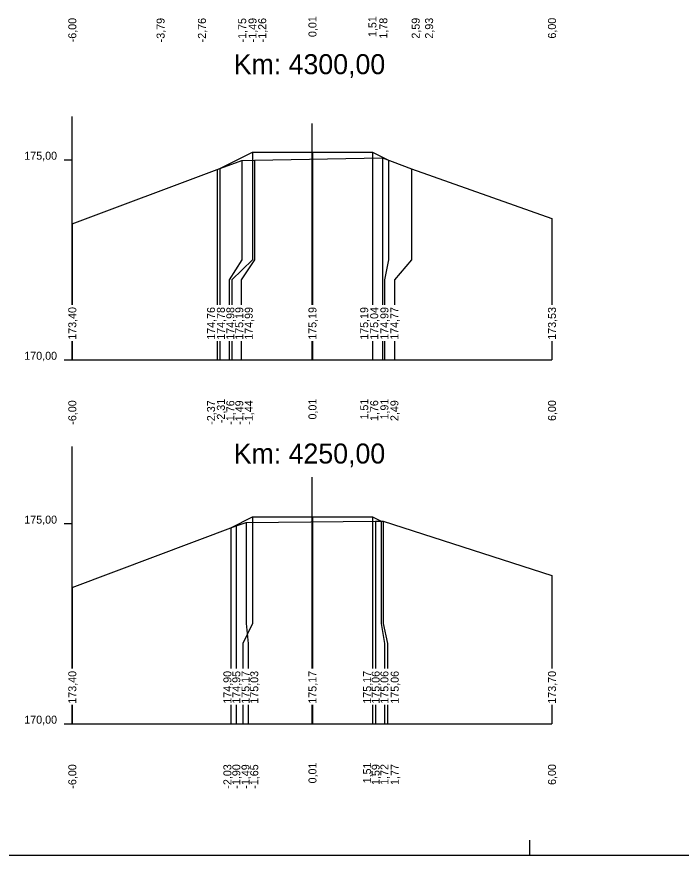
# Model space of a CAD drawing. Extents: x -614174 to -599765, y -1185887 to -1181080.
# Drawn here: x -600977.78 to -600961.16, y -1184533.61 to -1184512.65 of the extents above; entities that cross this region are included whole.
import ezdxf

# ---------------------------------------------------------------- set-up
doc = ezdxf.new("R2010")
doc.units = 0
for name, color, linetype in [('11', 7, 'Continuous'), ('16', 7, 'Continuous'), ('21', 7, 'Continuous'), ('28', 7, 'Continuous'), ('59', 7, 'Continuous'), ('8', 7, 'Continuous'), ('návrh', 7, 'Continuous')]:
    doc.layers.add(name, color=color, linetype=linetype)

msp = doc.modelspace()

# ---------------------------------------------------------------- linework, layer by layer
for points in [[(-600972.699, -1184516.446), (-600971.881, -1184516.037), (-600970.381, -1184516.037), (-600968.881, -1184516.037), (-600968.476, -1184516.239)], [(-600971.881, -1184516.037), (-600971.881, -1184516.037), (-600971.881, -1184516.037)], [(-600970.381, -1184516.037), (-600970.381, -1184516.037), (-600970.381, -1184516.037)], [(-600968.881, -1184516.037), (-600968.881, -1184516.037), (-600968.881, -1184516.037)], [(-600976.389, -1184517.827), (-600972.762, -1184516.469), (-600972.148, -1184516.243), (-600971.829, -1184516.236), (-600968.631, -1184516.182), (-600967.904, -1184516.452), (-600964.389, -1184517.699)], [(-600972.699, -1184516.446), (-600972.699, -1184516.446), (-600972.7, -1184516.446)], [(-600976.389, -1184526.919), (-600972.286, -1184525.374), (-600972.042, -1184525.291), (-600968.8, -1184525.264), (-600968.616, -1184525.264), (-600964.389, -1184526.622)], [(-600972.419, -1184525.424), (-600971.881, -1184525.156), (-600970.381, -1184525.156), (-600968.881, -1184525.156), (-600968.664, -1184525.264)], [(-600971.881, -1184525.156), (-600971.881, -1184525.156), (-600971.881, -1184525.156)], [(-600970.381, -1184525.156), (-600970.381, -1184525.156), (-600970.381, -1184525.156)], [(-600968.881, -1184525.156), (-600968.881, -1184525.156), (-600968.881, -1184525.156)], [(-600972.419, -1184525.424), (-600972.419, -1184525.424), (-600972.419, -1184525.424)]]:
    msp.add_lwpolyline(points)
at = {"layer": '11'}
for points in [[(-600971.881, -1184516.037), (-600971.881, -1184518.726), (-600972.399, -1184519.226), (-600972.399, -1184519.849)], [(-600970.381, -1184516.037), (-600970.381, -1184518.726), (-600970.381, -1184519.226), (-600970.381, -1184519.849)], [(-600968.881, -1184516.037), (-600968.881, -1184518.726), (-600968.881, -1184519.226), (-600968.881, -1184519.849)], [(-600972.148, -1184516.243), (-600972.148, -1184518.726), (-600972.462, -1184519.226), (-600972.462, -1184519.849)], [(-600971.829, -1184516.236), (-600971.829, -1184518.726), (-600972.162, -1184519.226), (-600972.162, -1184519.849)], [(-600968.631, -1184516.182), (-600968.631, -1184518.726), (-600968.631, -1184519.226), (-600968.631, -1184519.849)], [(-600968.476, -1184516.239), (-600968.476, -1184518.726), (-600968.581, -1184519.226), (-600968.581, -1184519.849)], [(-600972.762, -1184516.469), (-600972.762, -1184518.726), (-600972.762, -1184519.226), (-600972.762, -1184519.849)], [(-600972.699, -1184516.446), (-600972.699, -1184518.726), (-600972.699, -1184519.226), (-600972.699, -1184519.849)], [(-600967.904, -1184516.452), (-600967.904, -1184518.726), (-600968.331, -1184519.226), (-600968.331, -1184519.849)], [(-600964.389, -1184517.699), (-600964.389, -1184518.726), (-600964.389, -1184519.226), (-600964.389, -1184519.849)], [(-600976.389, -1184517.827), (-600976.389, -1184518.726), (-600976.389, -1184519.226), (-600976.389, -1184519.849)], [(-600976.389, -1184520.757), (-600976.389, -1184521.226)], [(-600972.762, -1184520.757), (-600972.762, -1184521.226)], [(-600972.699, -1184520.757), (-600972.699, -1184521.226)], [(-600972.462, -1184520.757), (-600972.462, -1184521.226)], [(-600972.399, -1184520.757), (-600972.399, -1184521.226)], [(-600972.162, -1184520.757), (-600972.162, -1184521.226)], [(-600970.381, -1184520.757), (-600970.381, -1184521.226)], [(-600968.881, -1184520.757), (-600968.881, -1184521.226)], [(-600968.631, -1184520.757), (-600968.631, -1184521.226)], [(-600968.581, -1184520.757), (-600968.581, -1184521.226)], [(-600968.331, -1184520.757), (-600968.331, -1184521.226)], [(-600964.389, -1184520.757), (-600964.389, -1184521.226)], [(-600971.881, -1184525.156), (-600971.881, -1184527.822), (-600972.119, -1184528.322), (-600972.119, -1184528.945)], [(-600972.042, -1184525.291), (-600972.042, -1184527.822), (-600971.986, -1184528.322), (-600971.986, -1184528.945)], [(-600970.381, -1184525.156), (-600970.381, -1184527.822), (-600970.381, -1184528.322), (-600970.381, -1184528.945)], [(-600968.881, -1184525.156), (-600968.881, -1184527.822), (-600968.881, -1184528.322), (-600968.881, -1184528.945)], [(-600968.8, -1184525.264), (-600968.8, -1184527.822), (-600968.8, -1184528.322), (-600968.8, -1184528.945)], [(-600968.664, -1184525.264), (-600968.664, -1184527.822), (-600968.581, -1184528.322), (-600968.581, -1184528.945)], [(-600968.616, -1184525.264), (-600968.616, -1184527.822), (-600968.5, -1184528.322), (-600968.5, -1184528.945)], [(-600972.419, -1184525.424), (-600972.419, -1184527.822), (-600972.419, -1184528.322), (-600972.419, -1184528.945)], [(-600972.286, -1184525.374), (-600972.286, -1184527.822), (-600972.286, -1184528.322), (-600972.286, -1184528.945)], [(-600964.389, -1184526.622), (-600964.389, -1184527.822), (-600964.389, -1184528.322), (-600964.389, -1184528.945)], [(-600976.389, -1184526.919), (-600976.389, -1184527.822), (-600976.389, -1184528.322), (-600976.389, -1184528.945)], [(-600976.389, -1184529.853), (-600976.389, -1184530.322)], [(-600972.419, -1184529.853), (-600972.419, -1184530.322)], [(-600972.286, -1184529.853), (-600972.286, -1184530.322)], [(-600972.119, -1184529.853), (-600972.119, -1184530.322)], [(-600971.986, -1184529.853), (-600971.986, -1184530.322)], [(-600970.381, -1184529.853), (-600970.381, -1184530.322)], [(-600968.881, -1184529.853), (-600968.881, -1184530.322)], [(-600968.8, -1184529.853), (-600968.8, -1184530.322)], [(-600968.581, -1184529.853), (-600968.581, -1184530.322)], [(-600968.5, -1184529.853), (-600968.5, -1184530.322)], [(-600964.389, -1184529.853), (-600964.389, -1184530.322)]]:
    msp.add_lwpolyline(points, dxfattribs=at)
at = {"layer": '16'}
for p, q in [((-600976.389, -1184521.226), (-600964.389, -1184521.226)), ((-600976.389, -1184530.322), (-600964.389, -1184530.322))]:
    msp.add_line(p, q, dxfattribs=at)
for points in [[(-600968.476, -1184516.239), (-600968.476, -1184516.239), (-600968.476, -1184516.239)], [(-600968.664, -1184525.264), (-600968.664, -1184525.264), (-600968.664, -1184525.264)]]:
    msp.add_lwpolyline(points, dxfattribs=at)
at = {"layer": '21'}
for p, q in [((-600976.589, -1184516.226), (-600976.389, -1184516.226)), ((-600976.589, -1184521.226), (-600976.389, -1184521.226)), ((-600976.589, -1184525.322), (-600976.389, -1184525.322)), ((-600976.589, -1184530.322), (-600976.389, -1184530.322))]:
    msp.add_line(p, q, dxfattribs=at)
at = {"layer": '28'}
for p, q in [((-600970.389, -1184519.849), (-600970.389, -1184515.319)), ((-600970.389, -1184521.226), (-600970.389, -1184520.757)), ((-600970.389, -1184528.945), (-600970.389, -1184524.163)), ((-600970.389, -1184530.322), (-600970.389, -1184529.853))]:
    msp.add_line(p, q, dxfattribs=at)
at = {"layer": '8'}
for p, q in [((-600976.389, -1184519.849), (-600976.389, -1184515.148)), ((-600976.389, -1184521.226), (-600976.389, -1184520.757)), ((-600976.389, -1184528.945), (-600976.389, -1184523.397)), ((-600976.389, -1184530.322), (-600976.389, -1184529.853))]:
    msp.add_line(p, q, dxfattribs=at)
at = {"layer": 'návrh'}
for p, q in [((-600964.944, -1184533.61), (-600964.944, -1184533.23)), ((-600985.944, -1184533.61), (-600964.944, -1184533.61)), ((-600964.944, -1184533.61), (-600943.944, -1184533.61))]:
    msp.add_line(p, q, dxfattribs=at)

# ---------------------------------------------------------------- texts
at = {"layer": '16'}
for s, p in [('173,40', (-600976.289, -1184520.726)), ('174,76', (-600972.818, -1184520.726)), ('174,78', (-600972.572, -1184520.726)), ('174,98', (-600972.335, -1184520.726)), ('175,19', (-600972.112, -1184520.726)), ('174,99', (-600971.875, -1184520.726)), ('175,19', (-600970.281, -1184520.726)), ('175,19', (-600968.986, -1184520.726)), ('175,04', (-600968.736, -1184520.726)), ('174,99', (-600968.481, -1184520.726)), ('174,77', (-600968.231, -1184520.726)), ('173,53', (-600964.289, -1184520.726)), ('173,40', (-600976.289, -1184529.822)), ('174,90', (-600972.409, -1184529.822)), ('174,95', (-600972.186, -1184529.822)), ('175,17', (-600971.956, -1184529.822)), ('175,03', (-600971.737, -1184529.822)), ('175,17', (-600970.281, -1184529.822)), ('175,17', (-600968.913, -1184529.822)), ('175,06', (-600968.7, -1184529.822)), ('175,06', (-600968.481, -1184529.822)), ('175,06', (-600968.223, -1184529.822)), ('173,70', (-600964.289, -1184529.822))]:
    msp.add_text(s, height=0.2, rotation=90, dxfattribs=at).set_placement(p)
at = {"layer": '21'}
for s, p in [('175,00', (-600977.589, -1184516.226)), ('170,00', (-600977.589, -1184521.226)), ('175,00', (-600977.589, -1184525.322)), ('170,00', (-600977.589, -1184530.322))]:
    msp.add_text(s, height=0.2, dxfattribs=at).set_placement(p)
at = {"layer": '28'}
for s, p in [('Km: 4300,00', (-600972.352, -1184514.088)), ('Km: 4250,00', (-600972.352, -1184523.82))]:
    msp.add_text(s, height=0.5, dxfattribs=at).set_placement(p)
at = {"layer": '59'}
for s, p in [('-6,00', (-600976.289, -1184513.291)), ('-3,79', (-600974.08, -1184513.292)), ('-2,76', (-600973.046, -1184513.292)), ('-1,75', (-600972.039, -1184513.294)), ('-1,49', (-600971.781, -1184513.292)), ('-1,26', (-600971.538, -1184513.292)), ('0,01', (-600970.281, -1184513.16)), ('1,51', (-600968.781, -1184513.16)), ('1,78', (-600968.508, -1184513.199)), ('2,59', (-600967.698, -1184513.199)), ('2,93', (-600967.363, -1184513.199)), ('6,00', (-600964.289, -1184513.198)), ('-6,00', (-600976.289, -1184522.849)), ('-2,37', (-600972.818, -1184522.85)), ('-2,31', (-600972.572, -1184522.811)), ('-1,76', (-600972.335, -1184522.85)), ('-1,49', (-600972.112, -1184522.851)), ('-1,44', (-600971.875, -1184522.849)), ('0,01', (-600970.281, -1184522.719)), ('1,51', (-600968.986, -1184522.719)), ('1,76', (-600968.736, -1184522.757)), ('1,91', (-600968.481, -1184522.719)), ('2,49', (-600968.231, -1184522.758)), ('6,00', (-600964.289, -1184522.756)), ('-6,00', (-600976.289, -1184531.946)), ('-2,03', (-600972.409, -1184531.946)), ('-1,90', (-600972.186, -1184531.946)), ('-1,49', (-600971.956, -1184531.947)), ('-1,65', (-600971.737, -1184531.948)), ('0,01', (-600970.281, -1184531.815)), ('1,51', (-600968.913, -1184531.815)), ('1,59', (-600968.7, -1184531.854)), ('1,72', (-600968.481, -1184531.851)), ('1,77', (-600968.223, -1184531.853)), ('6,00', (-600964.289, -1184531.853))]:
    msp.add_text(s, height=0.2, rotation=90, dxfattribs=at).set_placement(p)

doc.saveas('drawing.dxf')
